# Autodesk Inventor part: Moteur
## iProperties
Shininess: 64.0
Length Units: 11269
Angle Units: 11279
Time Units: 11290
Mass Units: 11283
Length Display Precision: 3
Angle Display Precision: 2
Compacted: True
Part Number: Moteur
Document SubType Name: Modeling
Created: 2003-05
Material: Par défaut
Designer: Philippe
Density: 0.0
Volumn: 0.0
Area: 0.0
PropertySet Name: Model Information
Control State: 0
Master: False
Checked Out: False
Author: Philippe
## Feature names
1. Révolution1 [Revolution]
2. Perçage1 [Hole]
3. Réseau circulaire1 [Circular Pattern]
4. Révolution2 [Revolution]
5. Extrusion1
6. Perçage2 [Hole]
7. Réseau circulaire2 [Circular Pattern]
